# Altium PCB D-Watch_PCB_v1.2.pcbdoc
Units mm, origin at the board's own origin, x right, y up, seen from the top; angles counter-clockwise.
Board outline 65.22 x 50.21 mm, 4 copper layers (Top Layer, Inner1, Inner2, Bottom Layer); 63 components, 51 nets, 243 pads, 70 vias.
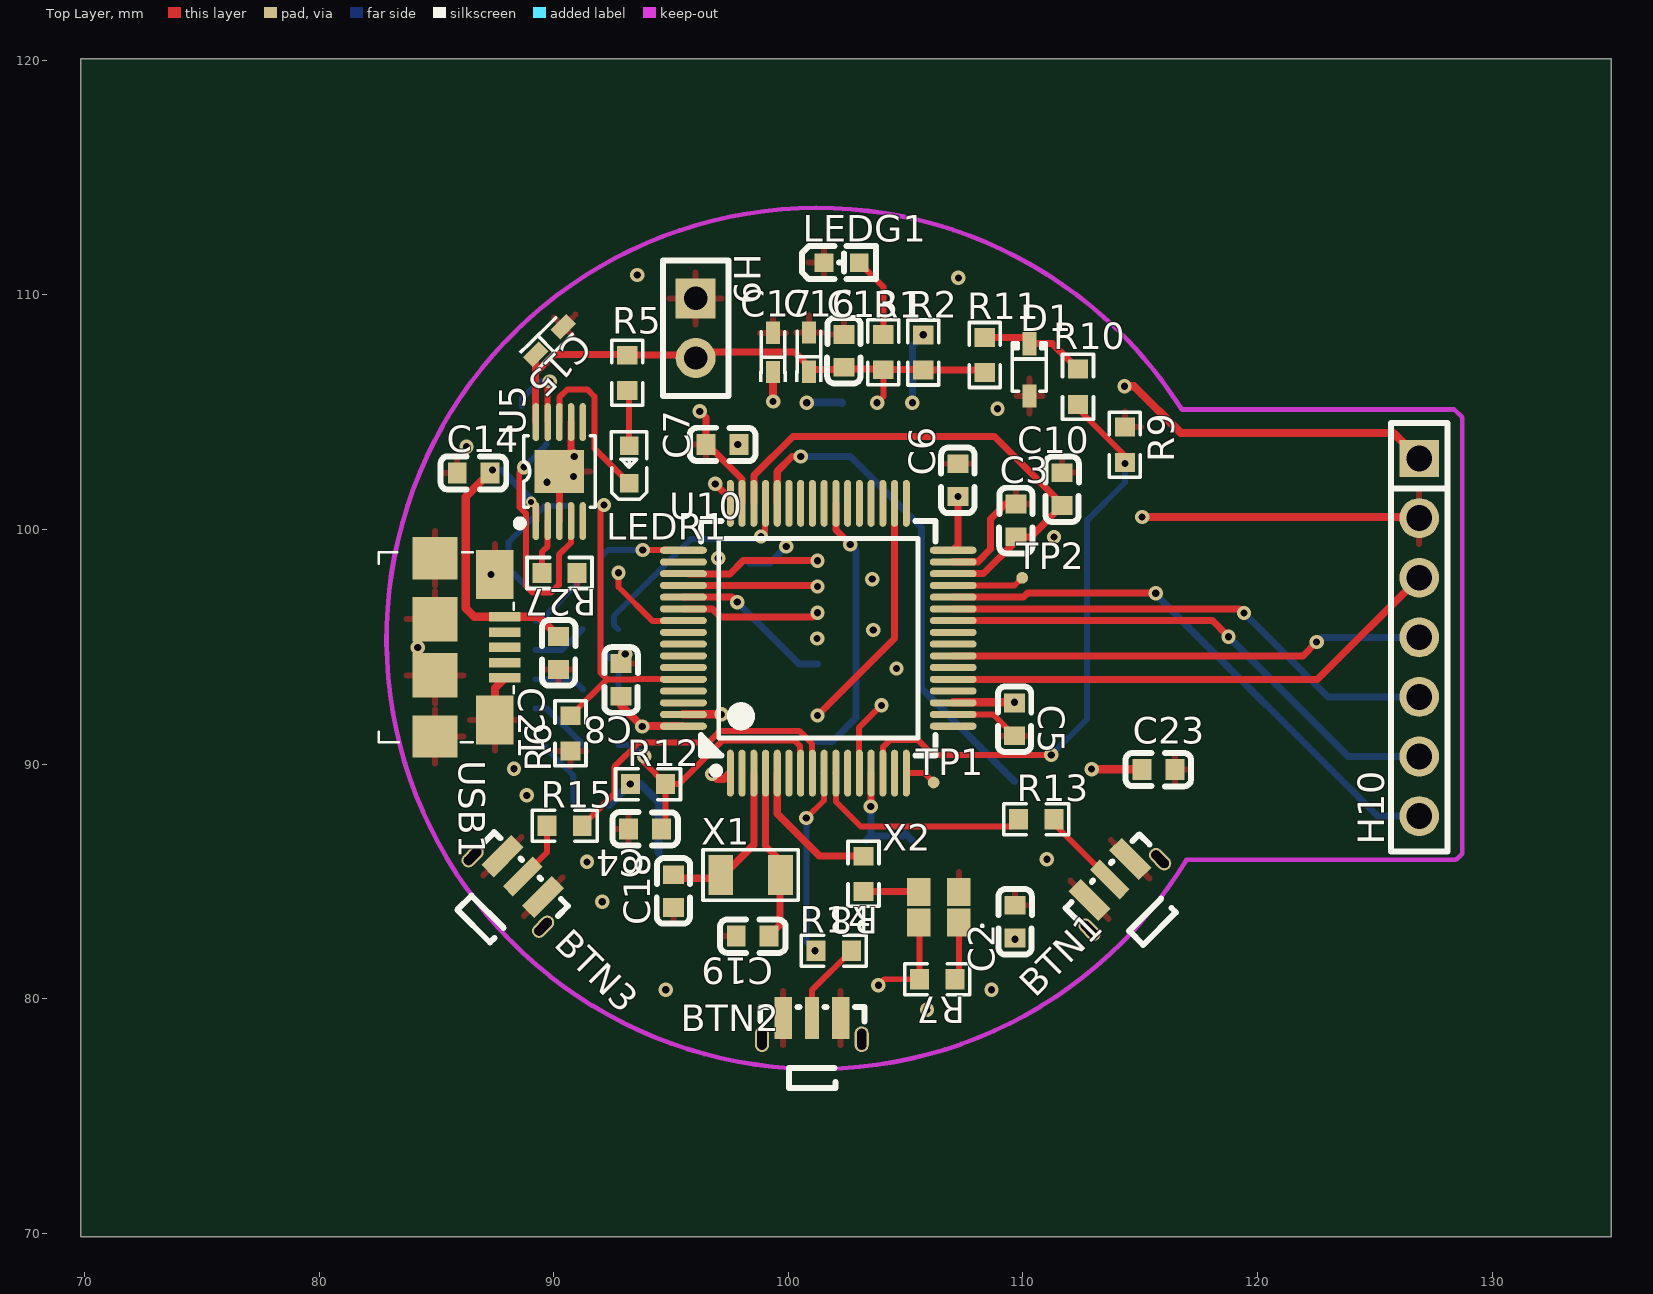
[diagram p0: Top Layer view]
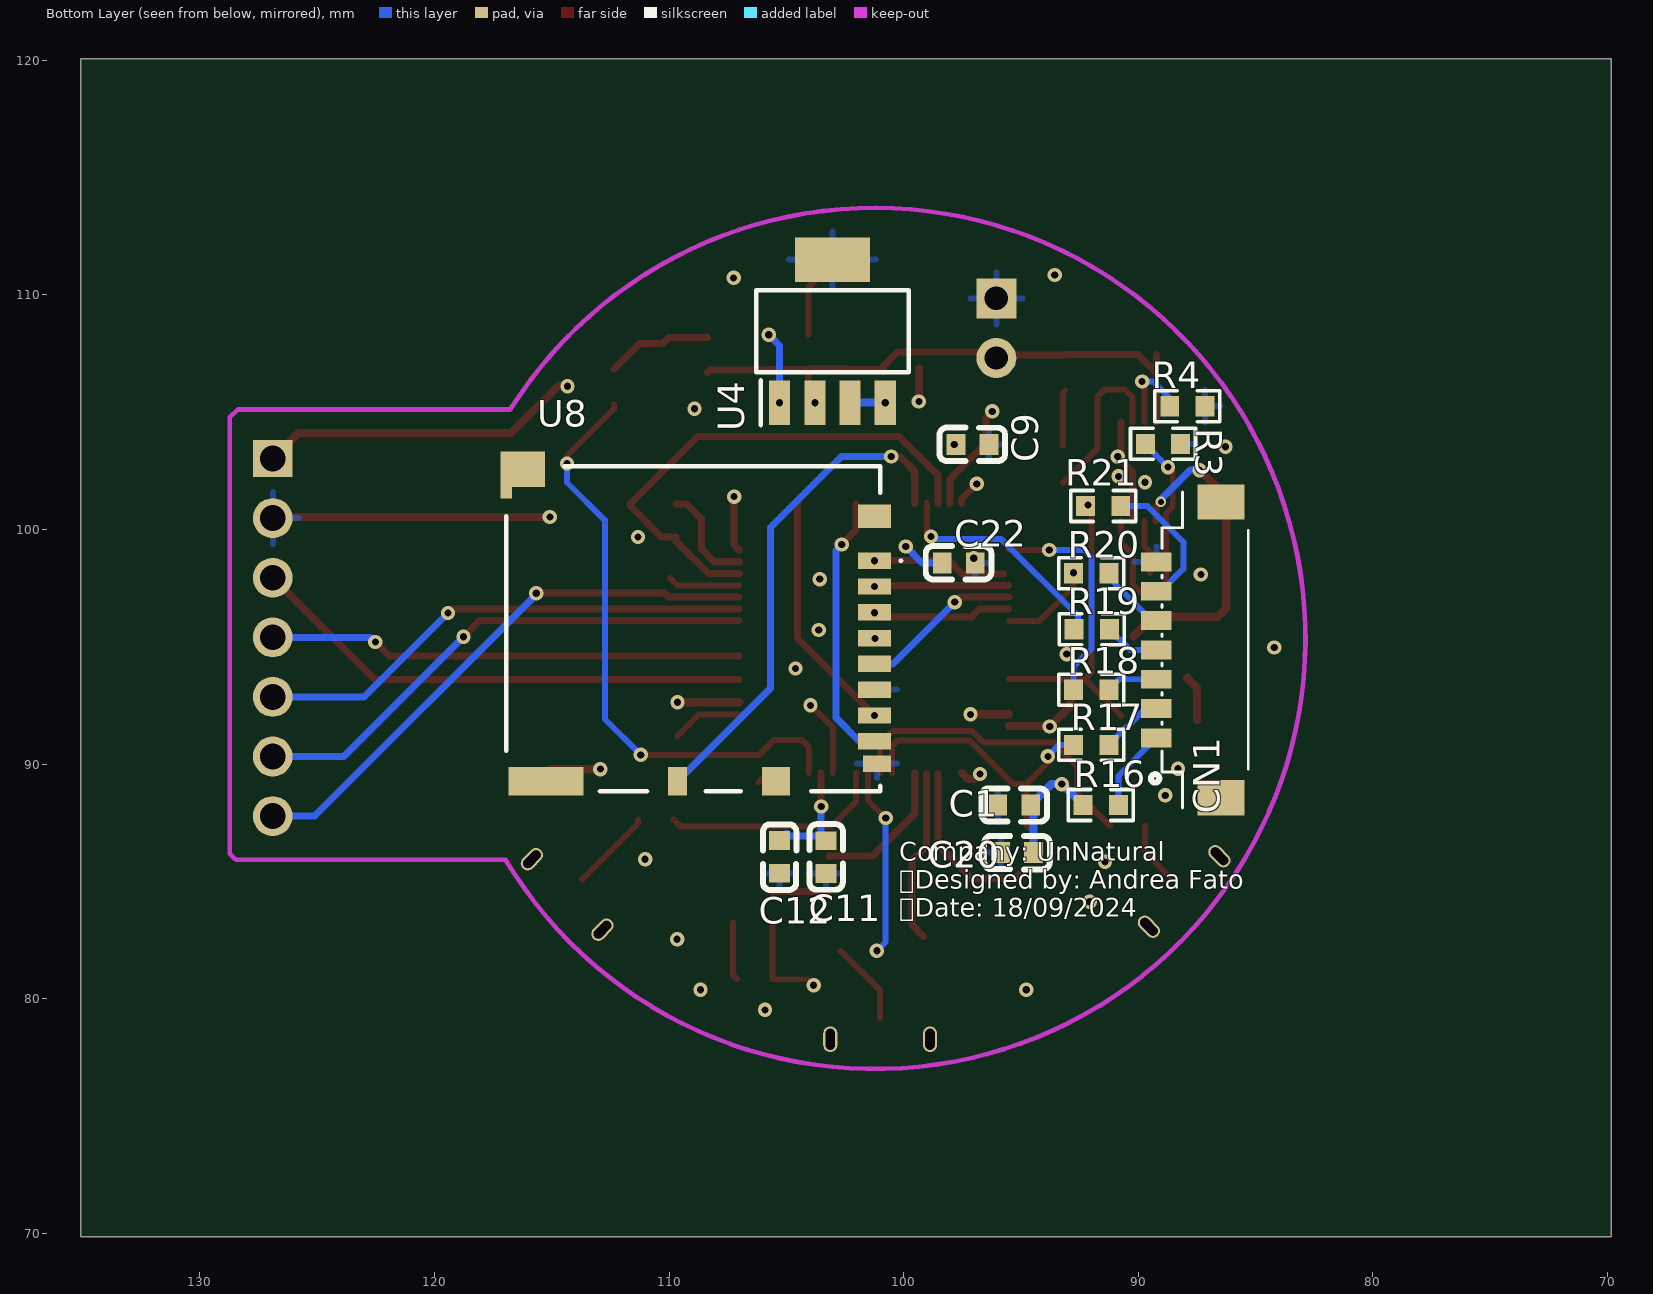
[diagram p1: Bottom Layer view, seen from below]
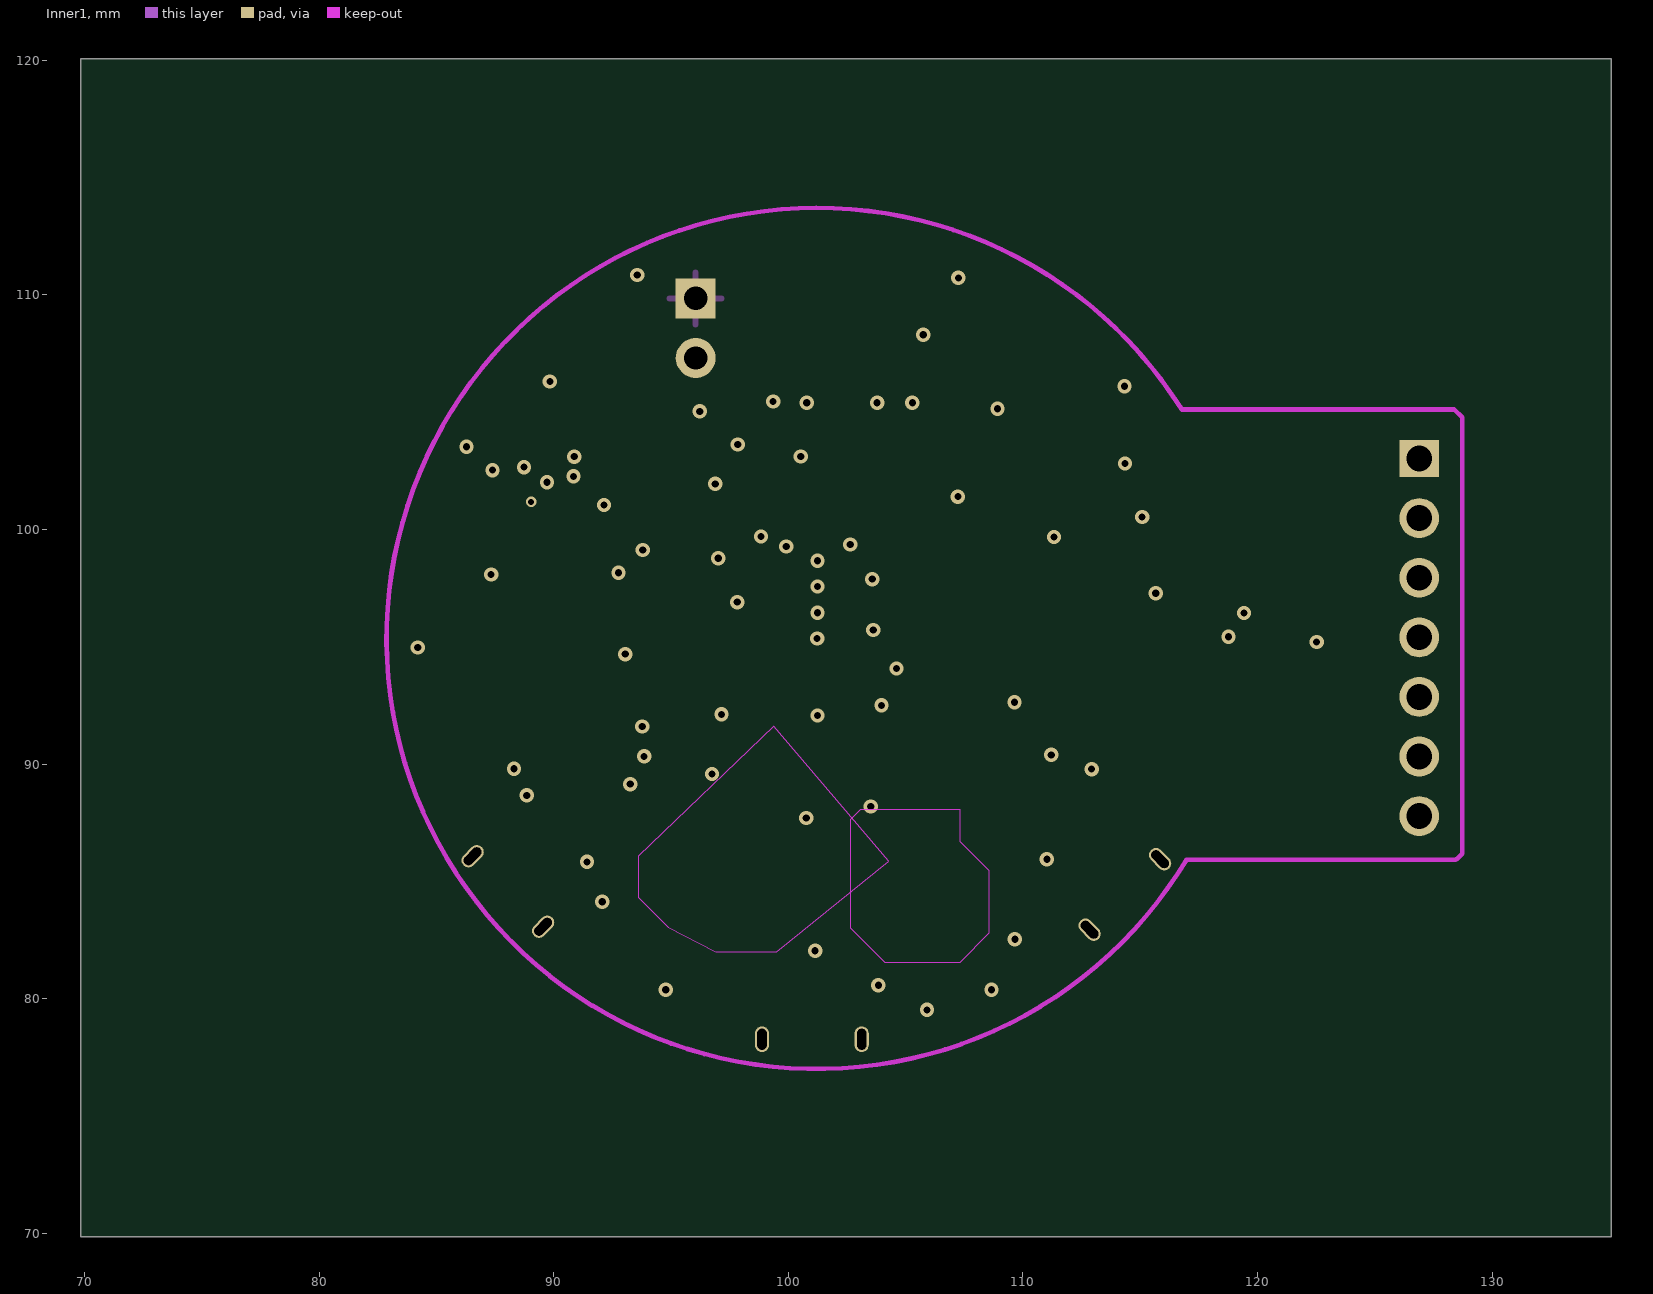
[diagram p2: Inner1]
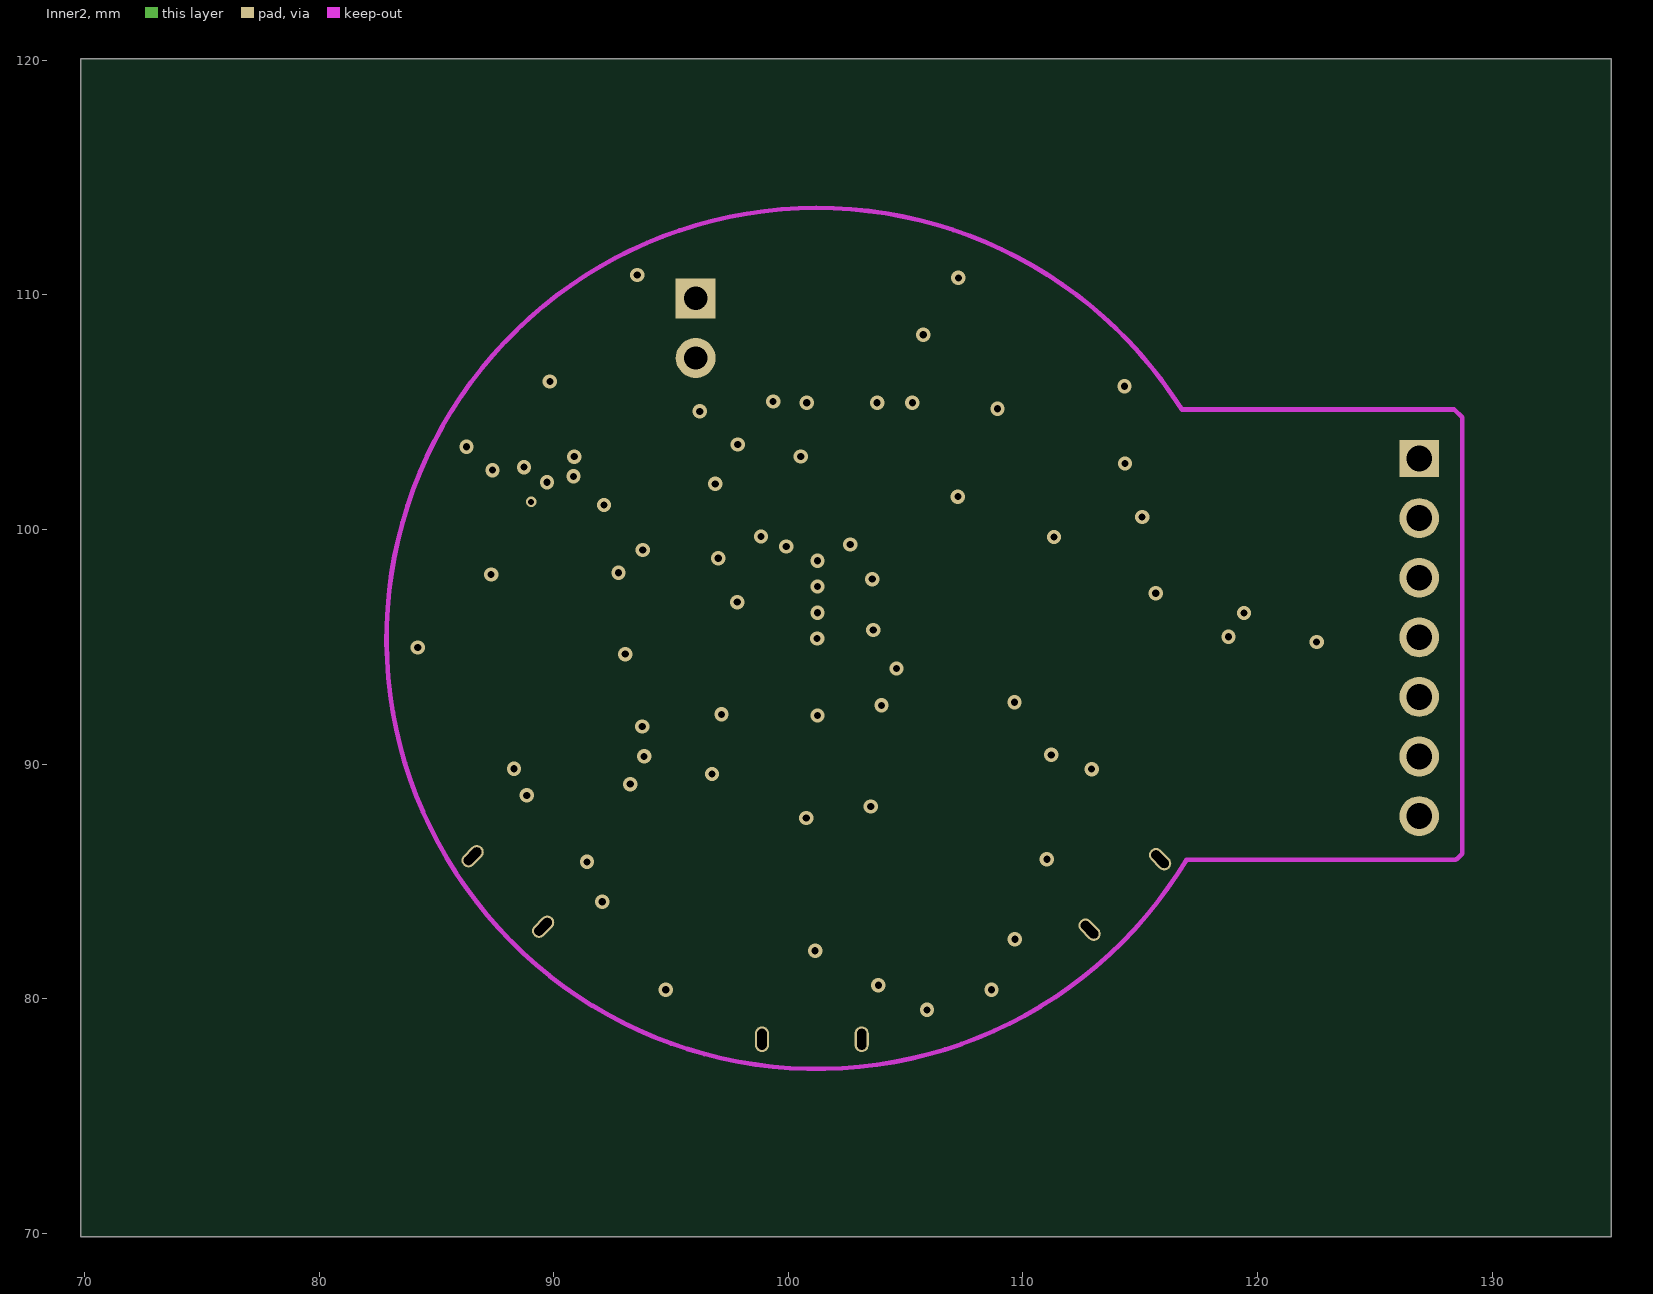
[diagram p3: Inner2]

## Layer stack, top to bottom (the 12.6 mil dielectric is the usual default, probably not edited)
Top Layer: signal copper (thickness not stored)
Dielectric: dielectric 0.32, FR-4, Dk 4.8
Inner1: signal copper (thickness not stored)
Dielectric: dielectric 0.32, FR-4, Dk 4.8
Inner2: signal copper (thickness not stored)
Dielectric: dielectric 0.32, FR-4, Dk 4.8
Bottom Layer: signal copper (thickness not stored)

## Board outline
135.07,69.85 69.85,69.85 69.85,120.059 135.07,120.059

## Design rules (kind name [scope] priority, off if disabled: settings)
Clearance copperThickness1oz [All] p1: gap=0.178 ignorepadtopadclearanceinfootprint=FALSE except(0.01: SMDPad-SMDPad; 0.102: Track-Track; 0.152: Track-SMDPad Track-THPad SMDPad-THPad THPad-THPad Track-Via SMDPad-Via THPad-Via Via-Via Track-Fill SMDPad-Fill THPad-Fill Via-Fill Fill-Fill SMDPad-Region THPad-Region Via-Region Fill-Region Region-Region Track-Poly SMDPad-Poly THPad-Poly Via-Poly Fill-Poly Poly-Poly Track-Text SMDPad-Text THPad-Text Via-Text Fill-Text Region-Text Poly-Text Text-Text; 0.175: Track-Hole SMDPad-Hole THPad-Hole Via-Hole Fill-Hole Region-Hole Poly-Hole Text-Hole Sheet-Hole; 0.3: Track-Region Region-Poly Track-Sheet SMDPad-Sheet THPad-Sheet Via-Sheet Fill-Sheet Region-Sheet Poly-Sheet Text-Sheet)
Clearance copperThickness2oz [All] p1: gap=0.178 ignorepadtopadclearanceinfootprint=FALSE except(0.152: Track-SMDPad SMDPad-SMDPad Track-THPad SMDPad-THPad THPad-THPad Track-Via SMDPad-Via THPad-Via Via-Via SMDPad-Fill THPad-Fill Via-Fill Fill-Fill Track-Region SMDPad-Region THPad-Region Via-Region Region-Region Track-Poly SMDPad-Poly THPad-Poly Via-Poly Fill-Poly Region-Poly Poly-Poly Track-Text SMDPad-Text THPad-Text Via-Text Fill-Text Region-Text Poly-Text Text-Text; 0.175: Track-Hole SMDPad-Hole THPad-Hole Via-Hole Fill-Hole Region-Hole Poly-Hole Text-Hole Sheet-Hole; 0.203: Track-Track; 0.3: Track-Fill Fill-Region Track-Sheet SMDPad-Sheet THPad-Sheet Via-Sheet Fill-Sheet Region-Sheet Poly-Sheet Text-Sheet)
Clearance BGA [All] p1: gap=0.178 ignorepadtopadclearanceinfootprint=FALSE except(0.099: Track-Track Track-SMDPad SMDPad-SMDPad Track-THPad SMDPad-THPad THPad-THPad Track-Via SMDPad-Via THPad-Via Via-Via Track-Fill SMDPad-Fill THPad-Fill Via-Fill Fill-Fill Track-Region SMDPad-Region THPad-Region Via-Region Fill-Region Region-Region Track-Poly SMDPad-Poly THPad-Poly Via-Poly Fill-Poly Region-Poly Poly-Poly Track-Hole SMDPad-Hole THPad-Hole Via-Hole Fill-Hole Region-Hole Poly-Hole Text-Hole Sheet-Hole; 0.152: Track-Text SMDPad-Text THPad-Text Via-Text Fill-Text Region-Text Poly-Text Text-Text; 0.3: Track-Sheet SMDPad-Sheet THPad-Sheet Via-Sheet Fill-Sheet Region-Sheet Poly-Sheet Text-Sheet)
DiffPairsRouting differentialPair [All] p1: maxuncoupledlength=10 maxlimit=5.9843 mostfreqgap=5.9843 toplayer_minwidth=5 toplayer_prefwidth=10 toplayer_maxwidth=100 bottomlayer_minwidth=5 bottomlayer_prefwidth=10 bottomlayer_maxwidth=100 midlayer1_minwidth=5 midlayer1_prefwidth=10 midlayer1_maxwidth=100 midlayer2_minwidth=5 midlayer2_prefwidth=10 midlayer2_maxwidth=100
PasteMaskExpansion pasteMaskExpansion [All] p1:
PlaneConnect innerPlane [All] p1: planeconnectstyle=Relief reliefexpansion=0.508 reliefentries=4 reliefconductorwidth=0.254 reliefairgap=0.254
PolygonConnect copperRegion [All] p1: connectstyle=Relief reliefentries=4 reliefconductorwidth=10 polygonreliefangle="90 Angle" airgapwidth=10
PolygonConnect copperRegionOSC [All] p1: connectstyle=Relief reliefentries=4 reliefconductorwidth=10 polygonreliefangle="90 Angle" airgapwidth=10
RoutingVias viaSize [All] p1: viastyle="Through Hole" holewidth=12.0078 minholewidth=5.9056 maxholewidth=248.0314 width=24.0158 minwidth=9.8426 maxwidth=393.7008
SolderMaskExpansion solderMaskExpansion [All] p1: useseparateexpansions=TRUE expansion=2.0079 expansionbottom=2.0079
Width copperThickness1oz [All] p1: maxlimit=100 minlimit=4 preferedwidth=10
Width copperThickness2oz [All] p1: maxlimit=100 minlimit=8 preferedwidth=10

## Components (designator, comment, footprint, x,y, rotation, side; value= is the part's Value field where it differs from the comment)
BTN1 "436333033816" SW-SMD_436333033816 114.467,84.323 r45 top
BTN2 "436333033816" SW-SMD_436333033816 101.005,78.1 r0 top
BTN3 "436333033816" SW-SMD_436333033816 87.924,84.45 r315 top
C1 "GCJ188R71C104KA01D" C0603 95.29,88.26 r0 bottom
C2 "GCJ188R71C104KA01D" C0603 109.67,83.286 r90 top
C3 "GCJ188R71C104KA01D" C0603 109.703,100.39 r90 top
C4 "GCJ188R71C104KA01D" C0603 93.893,87.244 r180 top
C5 "GCJ188R71C104KA01D" C0603 109.64,91.906 r270 top
C6 "GCJ188R71C104KA01D" C0603 107.228,102.103 r90 top
C7 "GCJ188R71C104KA01D" C0603 97.195,103.627 r180 top
C8 "GCJ188R71C104KA01D" C0603 92.877,93.594 r90 top
C9 "GCJ188C70J475KE02D" C0603 97.068,103.627 r180 bottom
C10 "GCJ188R71C104KA01D" C0603 111.673,101.722 r90 top
C11 "GCJ188R71C104KA01D" C0603 103.306,86.037 r270 bottom
C12 "CC0603KRX7R5BB105" C0603 105.286,86.047 r90 bottom
C13 "CC0603KRX7R5BB105" C0603 102.37,107.616 r270 top
C14 "CC0603KRX7R5BB105" C0603 86.59,102.406 r0 top
C15 "T58MM106M6R3C0300" CAP-SMD_L1.6-W0.8-RD 89.82,108.056 r225 top
C16 "T58MM106M6R3C0300" CAP-SMD_L1.6-W0.8-RD 100.878,107.564 r270 top
C17 "T58MM106M6R3C0300" CAP-SMD_L1.6-W0.8-RD 99.35,107.546 r270 top
C18 "CAP_0603" C0603 95.104,84.589 r270 top
C19 "CAP_0603" C0603 98.484,82.668 r180 top
C20 "AC0603KRX7R6BB105" C0603 95.163,86.228 r180 bottom
C21 "GCJ188R71C104KA01D" C0603 90.21,94.736 r270 top
C22 "GCJ188R71C104KA01D" C0603 97.655,98.579 r180 bottom
C23 "GCJ188R71C104KA01D" C0603 115.779,89.764 r0 top
CN1 "53398-0771" CONN-SMD_7P-P1.25_53398-0771 87.855,94.869 r90 bottom
D1 "TDZ3V6J,115" SOD-323_L1.7-W1.3-LS2.5-RD-1 110.276,106.802 r270 top
H9 "HDR-F_2.54_1x2P" HDR-TH_2P-P2.54-V-F 96.052,108.58 r270 top
H10 "HDR-F_2.54_1x7P" HDR-TH_7P-P2.54-V-F 126.89,95.406 r270 top
LEDG1 "APT1608MGC" LED-SMD_L1.6-W0.8-RD 102.275,111.374 r0 top
LEDR1 "APT1608SURCK" LED0603-RD 93.221,102.775 r90 top
R1 "Res_0603" R0603 104.053,107.564 r270 top
R2 "Res_0603" R0603 105.75,107.546 r90 top
R3 "Res_0603" R0603 88.95,103.649 r0 bottom
R4 "Res_0603" R0603 87.907,105.257 r180 bottom
R5 "Res_0603" R0603 93.131,106.675 r270 top
R6 "Res_0603" R0603 90.718,91.308 r90 top
R7 "Res_0603" R0603 106.35,80.833 r180 top
R8 "Res_0603" R0603 103.207,85.323 r90 top
R9 "Res_0603" R0603 114.349,103.618 r90 top
R10 "Res_0603" R0603 112.347,106.081 r90 top
R11 "Res_0603" R0603 108.371,107.437 r270 top
R12 "Res_0603" R0603 94.02,89.149 r0 top
R13 "Res_0603" R0603 110.566,87.649 r180 top
R14 "Res_0603" R0603 101.94,82.046 r180 top
R15 "Res_0603" R0603 90.464,87.371 r0 top
R16 "Res_0603" R0603 91.607,88.26 r180 bottom
R17 "Res_0603" R0603 92.012,90.821 r180 bottom
R18 "Res_0603" R0603 92.012,93.175 r180 bottom
R19 "Res_0603" R0603 91.988,95.753 r180 bottom
R20 "Res_0603" R0603 92.012,98.138 r180 bottom
R21 "Res_0603" R0603 91.504,101.001 r180 bottom
R27 "Res_0603" R0603 90.25,98.146 r180 top
TP1 "Test-Point" Test-Point-0.5mm 106.194,89.218 r0 top
TP2 "Test-Point" Test-Point-0.5mm 109.967,97.939 r0 top
U4 "LP3874EMP-3.3_NOPB_" SOT150P700X180-5N 103.037,108.453 r90 bottom
U5 "BQ24092DGQR" MSOP-10_L3.0-W3.0-P0.50-LS5.0-BL-EP 90.244,102.469 r0 top
U8 "DM3BT-DSF-PEJS_" DM3BTDSFPEJS 108.869,95.997 r270 bottom
U10 "STM32H7B0RBT6" LQFP-64_L10.0-W10.0-P0.50-LS12.0-BL 101.28,95.366 r0 top
USB1 "10118192-0001LF" MICRO-USB-SMD_10118192-0001LF_1 86.432,94.979 r270 top
X1 "NX3215SA-32.768K-STD-MUA-9" CRYSTAL-SMD_L3.2-W1.5-1 98.395,85.277 r0 top
X2 "EC5625ETTTS-25.000M_TR_" EC5625ETTTS25000MTR 106.42,83.906 r180 top

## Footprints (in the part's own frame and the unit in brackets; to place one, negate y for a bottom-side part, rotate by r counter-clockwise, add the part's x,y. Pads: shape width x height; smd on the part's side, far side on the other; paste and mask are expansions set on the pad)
C0603 [mm]
  rect 0.8x0.9 smd: 1(-0.7,0) 2(0.7,0)
  silkscreen extent -1.41,-0.71 1.39,0.72
CAP-SMD_L1.6-W0.8-RD [mm]
  rect 0.954x0.594 smd: 1(0.835,0) 2(-0.835,0)
  silkscreen extent -0.88,-0.58 1.26,0.58
CONN-SMD_7P-P1.25_53398-0771 [mm]
  rect 0.8x1.3 smd: 1(-3.75,1.375) 2(-2.5,1.375) 3(-1.25,1.375) 4(0,1.375) 5(1.25,1.375) 6(2.5,1.375) 7(3.75,1.375)
  rect 1.5x2 smd: 8(6.3,-1.375) 9(-6.3,-1.375)
  silkscreen extent -6.73,-2.54 6.73,1.61
CRYSTAL-SMD_L3.2-W1.5-1 [mm]
  rect 1.05x1.7 smd: 1(-1.275,0) 2(1.275,0)
  silkscreen extent -2.03,-1.08 2.03,1.08
DM3BTDSFPEJS [mm]
  rect 0.7x1.4 smd: 1(-2.675,7.625) 2(-1.575,7.625) 3(-0.475,7.625) 4(0.625,7.625) 5(1.725,7.625) 6(2.825,7.625) 7(3.925,7.625) 8(5.025,7.625)
  rect 1.2x0.8 smd: 9(6.725,-0.775)
  rect 0.7x1.2 smd: 10(5.975,7.725)
  rect 1x1.4 smd: 11(-4.575,7.625)
  rect 1.2x1.2 smd: 12(6.725,3.425)
  rect 1.2x3.2 smd: 13(6.725,-6.375)
  rect 1.5x1.9 smd: 14(-6.575,-7.375)
  rect 0.5x0.5 smd: 15(-5.575,-8.075)
  silkscreen extent -6.7,-8.07 7.15,8.8
EC5625ETTTS25000MTR [mm]
  rect 1x1.2 smd: 1(-0.85,0.65) 2(-0.85,-0.65) 3(0.85,-0.65) 4(0.85,0.65)
  silkscreen extent -1.9,0.75 -1.8,0.85
HDR-TH_2P-P2.54-V-F [mm]
  rect 1.7x1.7 hole 1: 1(-1.27,0)
  round 1.7 hole 1: 2(1.27,0)
  silkscreen extent -2.88,-1.39 2.88,1.4
HDR-TH_7P-P2.54-V-F [mm]
  rect 1.575x1.7 hole 1.1: 1(-7.62,0)
  round 1.7 hole 1.1: 2(-5.08,0) 3(-2.54,0) 4(0,0) 5(2.54,0) 6(5.08,0) 7(7.62,0)
  silkscreen extent -9.13,-1.2 9.13,1.2
LED0603-RD [mm]
  rect 0.8x0.8 smd: 1(-0.799,0) 2(0.799,0)
  silkscreen extent -1.49,-0.75 1.39,0.76
LED-SMD_L1.6-W0.8-RD [mm]
  rect 0.8x0.8 smd: 1(-0.75,0) 2(0.75,0)
  silkscreen extent -1.7,-0.7 1.47,0.7
LQFP-64_L10.0-W10.0-P0.50-LS12.0-BL [mm]
  oval 0.3x2 smd: 1(-3.75,-5.75) 2(-3.25,-5.75) 3(-2.75,-5.75) 4(-2.25,-5.75) 5(-1.75,-5.75) 6(-1.25,-5.75) 7(-0.75,-5.75) 8(-0.25,-5.75) 9(0.25,-5.75) 10(0.75,-5.75) 11(1.25,-5.75) 12(1.75,-5.75) 13(2.25,-5.75) 14(2.75,-5.75) 15(3.25,-5.75) 16(3.75,-5.75) 33(3.75,5.75) 34(3.25,5.75) 35(2.75,5.75) 36(2.25,5.75) 37(1.75,5.75) 38(1.25,5.75) 39(0.75,5.75) 40(0.25,5.75) 41(-0.25,5.75) 42(-0.75,5.75) 43(-1.25,5.75) 44(-1.75,5.75) 45(-2.25,5.75) 46(-2.75,5.75) 47(-3.25,5.75) 48(-3.75,5.75)
  oval 2x0.3 smd: 17(5.75,-3.75) 18(5.75,-3.25) 19(5.75,-2.75) 20(5.75,-2.25) 21(5.75,-1.75) 22(5.75,-1.25) 23(5.75,-0.75) 24(5.75,-0.25) 25(5.75,0.25) 26(5.75,0.75) 27(5.75,1.25) 28(5.75,1.75) 29(5.75,2.25) 30(5.75,2.75) 31(5.75,3.25) 32(5.75,3.75) 49(-5.75,3.75) 50(-5.75,3.25) 51(-5.75,2.75) 52(-5.75,2.25) 53(-5.75,1.75) 54(-5.75,1.25) 55(-5.75,0.75) 56(-5.75,0.25) 57(-5.75,-0.25) 58(-5.75,-0.75) 59(-5.75,-1.25) 60(-5.75,-1.75) 61(-5.75,-2.25) 62(-5.75,-2.75) 63(-5.75,-3.25) 64(-5.75,-3.75)
  silkscreen extent -5,-5.79 5,5
MICRO-USB-SMD_10118192-0001LF_1 [mm]
  rect 0.4x1.35 smd: 1(-1.3,1.487) 2(-0.65,1.487) 3(0,1.487) 4(0.65,1.487) 5(1.3,1.487)
  rect 1.8x1.9 smd: 6(-3.8,-1.487) 6(3.8,-1.487)
  rect 2.1x1.6 smd: 6(-3.1,1.063) 6(3.1,1.063)
  rect 1.9x1.9 smd: 6(-1.199,-1.487) 6(1.199,-1.487)
  silkscreen extent -4.05,-3.89 4.05,1.86
MSOP-10_L3.0-W3.0-P0.50-LS5.0-BL-EP [mm]
  oval 0.28x1.62 smd: 1(-1,-2.11) 2(-0.5,-2.11) 3(0,-2.11) 4(0.5,-2.11) 5(1,-2.11) 6(1,2.11) 7(0.5,2.11) 8(0,2.11) 9(-0.5,2.11) 10(-1,2.11)
  rect 2.1x1.83 smd: 11(0,0)
  silkscreen extent -1.84,-2.35 1.52,1.52
R0603 [mm]
  rect 0.806x0.864 smd: 1(-0.753,0) 2(0.753,0)
  silkscreen extent -1.39,-0.66 1.39,0.66
SOD-323_L1.7-W1.3-LS2.5-RD-1 [mm]
  rect 0.985x0.6 smd: 1(-1.118,0) 2(1.118,0)
  silkscreen extent -1.15,-0.73 0.9,0.73
SOT150P700X180-5N [mm]
  rect 1.9x0.9 smd: 1(-3.05,2.25) 2(-3.05,0.75) 3(-3.05,-0.75) 4(-3.05,-2.25)
  rect 1.9x3.2 smd: 5(3.05,0)
  silkscreen extent -4,-3.25 1.75,3.25
SW-SMD_436333033816 [mm]
  rect 0.75x1.8 smd: 1(-1.225,1.075) 3(1.225,1.075)
  rect 0.6x1.8 smd: 2(0,1.075)
  oval 0.6x1.1 hole 0.4 slot 0.9 at 90 deg: 6(-2.125,0.175) 6(2.125,0.175)
  silkscreen extent -2.2,-1.9 2.25,1.55
Test-Point-0.5mm [mm]
  round 0.5 smd: 1(0,0)

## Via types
v1: diameter 0.61, hole 0.305, Top Layer to Bottom Layer, 69 vias
v2: diameter 0.45, hole 0.25, Top Layer to Bottom Layer, 1 vias

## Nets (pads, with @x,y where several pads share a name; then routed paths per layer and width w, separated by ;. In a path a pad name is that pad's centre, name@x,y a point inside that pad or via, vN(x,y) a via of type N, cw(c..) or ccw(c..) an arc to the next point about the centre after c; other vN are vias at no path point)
5V_USB_CHGR: C14.2 C21.1 U5.1 USB1.1 | length 14
  Top Layer w0.3: v2(89.038,101.177) 89.244,100.971 U5.1
  Top Layer w0.35: v1(87.396,102.532) 86.25,101.386 86.25,96.646 86.617,96.279 87.858,96.279 USB1.1@87.87,96.291 ; USB1.1 89.367,96.279 C21.1
  Bottom Layer w0.3: v1(87.396,102.532) 87.41,102.546 87.78,102.546 89.038,101.288 v2(89.038,101.177)
$1N5489: R2.2 U4.1 | length 3.1
  Bottom Layer w0.3: v1(105.287,105.403) 105.287,107.836 v1(105.75,108.299)
$1N5967: R3.2 U5.4 | length 11.3
  Top Layer w0.254: v1(88.737,102.66) 88.534,102.457 88.534,100.968 88.814,100.688 88.814,97.598 89.107,97.306 89.886,97.306 90.224,97.644 90.224,98.92 90.74,99.436 90.74,100.355 U5.4
  Bottom Layer w0.254: v1(88.737,102.66) 89.704,103.627 R3.2
$1N5968: R27.2 U5.2 | length 2.3
  Top Layer w0.254: R27.2 89.497,99.042 89.744,99.29 U5.2
$1N5969: R4.1 U5.9 | length 3.6
  Top Layer w0.254: U5.9 89.744,106.213 v1(89.837,106.306)
  Bottom Layer w0.254: R4.1 88.661,105.596 89.37,106.306 v1(89.837,106.306)
$1N5973: LEDR1.1 U5.8 | length 7.1
  Top Layer w0.254: U5.8 90.244,105.63 90.59,105.976 91.43,105.976 91.735,105.671 91.735,103.462 LEDR1.1
$1N5974: LEDR1.2 R5.2 | length 2.4
  Top Layer w0.254: R5.2 93.221,105.832 LEDR1.2
$1N6463: LEDG1.2 R1.1 | length 3.5
  Top Layer w0.254: LEDG1.2 104.053,110.346 R1.1
$2N8217: R7.1 X2.1 | length 2.5
  Top Layer w0.254: R7.1 107.27,80.999 X2.1
$2N8264: R8.1 X2.3 | length 2.4
  Top Layer w0.3: R8.1 105.557,84.569 X2.3
$2N18890: D1.1 R10.2 R11.1 | length 4.5
  Top Layer w0.3: R11.1 110.005,108.19 D1.1 111.262,107.92 R10.2
$2N23973: TP1.1 U10.16 | length 1.4
  Top Layer w0.254: U10.16@105.009,89.622 105.789,89.622 TP1.1
$3N1058: CN1.1 R16.2 | length 3.5
  Bottom Layer w0.254: CN1.1 90.854,89.495 R16.2
$3N1061: CN1.2 R17.2 | length 2.7
  Bottom Layer w0.254: CN1.2 89.711,92.369 R17.2
$3N1065: CN1.3 R18.2 | length 2.2
  Bottom Layer w0.254: CN1.3 90.815,93.619 R18.2
$3N1094: CN1.4 R19.2 | length 2.4
  Bottom Layer w0.254: CN1.4 90.35,94.869 R19.2
$3N1097: CN1.5 R20.2 | length 3
  Bottom Layer w0.254: CN1.5 89.425,96.119 91.259,97.952 R20.2
$3N1126: CN1.6 R21.2 | length 6
  Bottom Layer w0.254: CN1.6 89.036,97.369 88.08,98.324 88.08,99.466 89.615,101.001 R21.2
$3N2256: BTN2.2 R14.1 | length 3.6
  Top Layer w0.254: BTN2.2 101.005,80.358 R14.1
$3N2358: BTN3.2 R15.1 | length 2.6
  Top Layer w0.254: BTN3.2 89.711,86.237 R15.1
$3N11256: BTN1.2 R13.1 | length 3.6
  Top Layer w0.254: R13.1 111.319,87.471 BTN1.2
+3V3: 
ADC1_IN16: R9.1 R10.1 U10.14 | length 25.7
  Top Layer w0.254: U10.14 104.03,90.716 104.35,91.036 105.52,91.036 106.16,90.396 v1(111.21,90.396) ; R10.1 112.347,105.144 114.349,103.142 v1(114.349,102.815)
  Bottom Layer w0.254: v1(111.21,90.396) 112.74,91.926 112.74,100.396 114.349,102.005 v1(114.349,102.815)
BOOT0: R6.2 R21.1 U10.60 | length 13
  Top Layer w0.254: R6.2 92.279,93.622 ; v1(92.144,101.041) 92,100.897 92,93.901 92.279,93.622 ; U10.60@95.509,93.622 93.45,93.622 93.443,93.615 92.312,93.615 92.305,93.622 92.279,93.622
GC9A01_BL: TP2.1 U10.29 | length 3.1
  Top Layer w0.254: U10.29 109.644,97.616 TP2.1
GC9A01_CS: H10.6 U10.26 | length 22.3
  Top Layer w0.3: U10.26 118.074,96.116 v1(118.76,95.43)
  Bottom Layer w0.3: v1(118.76,95.43) 123.864,90.326 H10.6
GC9A01_DC: H10.5 U10.27 | length 21.4
  Top Layer w0.3: U10.27 119.25,96.616 v1(119.42,96.446)
  Bottom Layer w0.3: v1(119.42,96.446) 123,92.866 H10.5
GC9A01_RST: H10.7 U10.28 | length 23.9
  Top Layer w0.3: U10.28 110.02,97.116 110.19,97.286 v1(115.66,97.286)
  Bottom Layer w0.3: v1(115.66,97.286) 115.66,97.236 125.11,87.786 H10.7
GND: BTN1.1 BTN1.3 BTN2.1 BTN2.3 BTN3.1 BTN3.3 C1.2 C2.2 C3.2 C4.2 C5.2 C6.2 C7.2 C8.2 C9.2 C10.2 C11.2 C12.1 C13.1 C14.1 C15.2 C16.2 C17.2 C18.2 C19.2 C20.1 C21.2 C22.2 C23.2 CN1.7 D1.2 H9.1 H10.2 LEDG1.1 R3.1 R4.2 R6.1 R9.2 R27.1 U4.5 U5.3 U5.7 U5.11 U8.6 U8.10 U10.12 U10.18 U10.31 U10.47 U10.63 USB1.5 USB1.6 X2.2 | length 35.3
  Top Layer w0.254: U10.12@103.009,89.622 103.009,91.545 v1(103.97,92.506) ; U10.18@107.009,92.122 108.724,92.122 C5.2
  Top Layer w0.3: U5.3 U5.11 90.744,102.969 U5.7 ; v1(96.225,105.037) 96.49,104.772 96.49,103.686 98.02,102.156 98.02,101.126 U10.47 ; U10.31@107.009,98.622 107.013,98.626 108.08,98.626 108.62,99.166 108.62,100.446 109.264,101.09 C3.2
  Top Layer w0.35: USB1.6@87.495,91.879 87.495,93.254 USB1.5 ; U10.63@95.509,92.122 v1(97.15,92.122) ; v1(115.08,100.536) 126.84,100.536 H10.2
  other v1: 105.91,79.526 94.78,80.386 92.07,84.136 91.42,85.836 111.02,85.946 88.853,88.67 88.309,89.806 104.61,94.076 93.052,94.689 84.206,94.972 103.62,95.716 103.58,97.886 87.335,98.079 97.016,98.774 111.323,99.68 89.72,102.016 90.848,102.265 90.88,103.106 86.289,103.527 108.914,105.144 107.25,110.726 93.56,110.846
MINUS_BTN: R13.2 U10.10 | length 9.6
  Top Layer w0.254: U10.10@102.009,89.622 102.03,89.601 102.03,88.405 103.1,87.336 109.499,87.336 R13.2
OSC32_IN: C18.1 U10.3 X1.1 | length 7.1
  Top Layer w0.3: C18.1@95.11,85.286 95.258,85.138 97.105,85.138 98.53,86.562 U10.3@98.53,89.601
OSC32_OUT: C19.1 U10.4 X1.2 | length 7.4
  Top Layer w0.3: U10.4@99.03,89.601 99.03,86.516 99.655,85.891 99.655,83.16 C19.1@99.152,82.657
OSC_25M: R8.2 U10.5 | length 6.2
  Top Layer w0.3: U10.5 99.53,87.886 101.34,86.076 R8.2
PLUS_BTN: R15.2 U10.8 | length 13.6
  Top Layer w0.254: R15.2 92.585,88.738 92.585,89.886 93.613,90.915 96.595,90.915 97.097,91.416 100.46,91.416 101.009,90.867 U10.8@101.009,89.622
RESET#: C4.1 R12.2 R17.1 U10.7 | length 12.6
  Top Layer w0.254: v1(93.855,90.331) 93.855,90.067 R12.2 ; C4.1 94.774,87.424 R12.2 ; U10.7@100.509,89.622 100.509,90.763 100.255,91.017 97.201,91.017 95.333,89.149 R12.2
  Bottom Layer w0.254: R17.1 93.365,90.821 v1(93.855,90.331)
SDIO1_CLK: U8.5 U10.53 | length 6.9
  Top Layer w0.3: U10.53@95.509,97.122 97.604,97.122 v1(97.822,96.904)
  Bottom Layer w0.3: v1(97.822,96.904) 100.454,94.272 U8.5
SDIO1_CMD: U8.3 U10.54 | length 5.9
  Top Layer w0.3: U10.54 96.771,96.615 97.12,96.266 101.061,96.266 v1(101.246,96.451)
SDIO1_D0: U8.7 U10.34 | length 10.4
  Top Layer w0.3: v1(101.244,92.072) 104.53,95.358 U10.34
SDIO1_D1: U8.8 U10.39 | length 11.6
  Top Layer w0.3: U10.39 102.03,99.972 v1(102.641,99.361)
  Bottom Layer w0.3: U8.8 101.886,90.972 102.89,91.976 102.89,99.112 v1(102.641,99.361)
SDIO1_D2: U8.1 U10.51 | length 5.7
  Top Layer w0.3: U10.51@95.757,98.114 95.766,98.106 97.51,98.106 98.074,98.67 v1@101.244,98.67
  other v1: 101.244,98.672
SDIO1_D3: U8.2 U10.52 | length 5.7
  Top Layer w0.254: v1@101.2,97.616 v1(101.244,97.572)
  Top Layer w0.3: U10.52 v1@101.2,97.616
SET_BTN: R14.2 U10.9 | length 8
  Top Layer w0.254: v1(100.769,87.702) 101.52,88.453 101.52,89.611 U10.9@101.509,89.622
  Bottom Layer w0.254: v1(100.769,87.702) 100.769,82.422 v1(101.145,82.046)
SPI1_MOSI: H10.4 U10.23 | length 20.2
  Top Layer w0.3: U10.23 121.93,94.616 v1(122.52,95.206)
  Bottom Layer w0.3: v1(122.52,95.206) 122.72,95.406 H10.4
SPI1_SCK: H10.3 U10.21 | length 21.7
  Top Layer w0.3: U10.21 122.56,93.616 H10.3
TCK/SWCLK: R18.1 U10.49 | length 9.6
  Top Layer w0.254: v1(93.8,99.126) 93.804,99.122 U10.49@95.509,99.122
  Bottom Layer w0.254: R18.1 92.765,94.151 92,94.916 92,98.816 92.31,99.126 v1(93.8,99.126)
TDO/SWO: R20.1 U10.55 | length 4
  Top Layer w0.254: v1(92.766,98.159) 92.766,97.55 94.22,96.096 95.483,96.096 U10.55@95.509,96.122
TMS/SWDIO: R19.1 U10.45 | length 9.8
  Top Layer w0.254: v1(98.841,99.702) 99.009,99.87 U10.45@99.009,101.122
  Bottom Layer w0.254: R19.1 92.572,95.923 92.572,96.317 95.846,99.592 98.731,99.592 v1(98.841,99.702)
USD_DETECT: U8.9 U10.44 | length 21.5
  Top Layer w0.3: U10.44 99.53,102.482 100.164,103.116 v1(100.533,103.116)
  Bottom Layer w0.3: v1(100.533,103.116) 102.65,103.116 105.68,100.086 105.68,93.235 U8.9
VBAT: C13.2 C15.1 C16.1 H9.2 R1.2 R2.1 R5.1 R11.2 U4.2 U5.10 | length 24.6
  Top Layer w0.254: U5.10@89.23,104.593 U5.10 ; v1(103.787,105.403) 104.053,105.669 R1.2
  Top Layer w0.3: U5.10@89.23,104.593 89.23,106.67 ; C15.1 89.23,106.67 ; R2.1 108.262,106.792 R11.2 ; R2.1@105.75,106.811 R1.2 104.028,106.836 102.39,106.836 102.365,106.811 100.96,106.811 C16.1 100.878,106.948 100.262,107.564 96.306,107.564 H9.2 95.934,107.428 R5.1 93.094,107.466 90.025,107.466 89.23,106.67
VCAP: C3.1 C10.1 U10.30 U10.46 | length 22.2
  Top Layer w0.3: U10.46 98.53,102.296 100.2,103.966 108.79,103.966 111.673,101.083 C10.1 110.341,99.69 C3.1 109.703,99.499 108.326,98.122 U10.30@107.009,98.122
VDDA: C11.1 C12.2 U10.13 | length 4.9
  Top Layer w0.3: v1(103.516,88.194) 103.53,88.208 U10.13
  Bottom Layer w0.3: C11.1 C11.1@103.505,86.936 ; v1(103.516,88.194) 103.516,86.947 C11.1@103.505,86.936 ; C12.2 104.996,87.037 104.895,86.936 C11.1@103.505,86.936
pads on no net: BTN1.6 BTN2.6 BTN3.6 C1.1 C2.1 C5.1 C6.1 C7.1 C8.1 C9.1 C17.1 C20.2 C22.1 C23.1 CN1.8 CN1.9 H10.1 R7.2 R12.1 R16.1 U4.3 U4.4 U5.5 U5.6 U8.4 U8.11 U8.12 U8.13 U8.14 U8.15 U10.1 U10.2 U10.6 U10.11 U10.15 U10.17 U10.19 U10.20 U10.22 U10.24 U10.25 U10.32 U10.33 U10.35 U10.36 U10.37 U10.38 U10.40 U10.41 U10.42 U10.43 U10.48 U10.50 U10.56 U10.57 U10.58 U10.59 U10.61 U10.62 U10.64 USB1.2 USB1.3 USB1.4 X2.4
copper on no net: | length 40.6
  Top Layer w0.254: v1(103.84,80.576) 104.097,80.833 105.597,80.833 105.597,83.229 105.57,83.256
  Top Layer w0.3: v1(96.886,101.946) 97.53,101.302 97.53,101.116 ; 107.009,99.122 107.228,99.341 v1(107.228,101.403)
  Top Layer w0.35: 92.877,92.894 92.877,92.501 v1(93.776,91.602) 93.796,91.622 95.509,91.622 ; v1(96.749,89.582) 96.965,89.366 97.253,89.366 97.509,89.622 ; v1(99.354,105.459) 99.354,106.856 ; 107.009,92.622 107.023,92.636 v1(109.641,92.636) ; v1(112.93,89.786) 112.932,89.784 115.059,89.784 115.079,89.764 ; v1(114.33,106.106) 114.74,106.106 116.73,104.116 125.8,104.116 126.89,103.026
  Bottom Layer w0.3: 98.355,98.579 99.217,98.579 v1(99.915,99.277)
  Bottom Layer w0.35: 92.361,88.26 93.25,89.149 v1(93.267,89.149) 93.701,89.149 94.59,88.26 94.463,88.133 94.463,86.228 ; v1(100.787,105.403) 100.792,105.408 102.282,105.408 102.287,105.403
  other v1: 108.66,80.386 109.658,82.539 101.229,95.359 97.845,103.621

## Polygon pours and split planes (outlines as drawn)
GND on Inner1 (solid, remove dead copper): 119.255,95.372 ccw(c101.244,95.372) 83.232,95.372 ccw(c101.244,95.372)
no net on Inner2 (solid, remove dead copper): 119.56,95.215 ccw(c101.549,95.171) 83.538,95.215 ccw(c101.549,95.259)
GND on Bottom Layer (solid, remove dead copper, pour order 4): 119.249,95.352 ccw(c101.204,95.314) 83.158,95.352 ccw(c101.204,95.389)
GND on Top Layer (solid, remove dead copper): 119.27,95.372 ccw(c101.259,95.345) 83.248,95.372 ccw(c101.259,95.399)
GND on Top Layer (solid, remove dead copper, pour order 2): 116.7,86.386 128.17,86.386 128.17,104.586 128.16,104.596 116.65,104.596 116.64,104.586 116.64,86.446
GND on Bottom Layer (solid, remove dead copper, pour order 6): 116.715,86.471 128.185,86.471 128.185,104.671 128.175,104.681 116.665,104.681 116.655,104.671 116.655,86.531

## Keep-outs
Inner1:
  region: 99.381,91.605 93.603,86.076 93.603,84.329 94.877,83.056 96.91,81.996 99.499,81.996 104.291,85.865
  region: 102.64,87.63 102.64,83.036 104.12,81.556 107.32,81.556 108.57,82.806 108.57,85.454 107.34,86.684 107.34,88.056 103.066,88.056
Board Outline Layer:
  lines w0.2: 116.76,105.126 116.77,105.116 ; 116.957,85.92 128.45,85.936 ; 116.963,85.916 cw(c101.229,95.359) 116.77,105.116 ; 128.49,85.946 128.72,86.176 128.72,104.786 128.39,105.116 116.77,105.116

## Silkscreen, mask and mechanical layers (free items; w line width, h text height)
Bottom Silkscreen Layer:
  text "Company: UnNatural /  Designed by: Andrea Fato /  Date: 18/09/2024" at 100.2,83.486 h0.8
